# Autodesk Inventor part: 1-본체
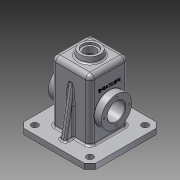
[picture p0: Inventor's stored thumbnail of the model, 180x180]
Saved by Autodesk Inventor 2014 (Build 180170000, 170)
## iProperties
Created: 2016-02
Part Number: 1-본체
Material: 알루미늄 6061
Document SubType Name: Modeling
Designer: HGY
Density: 2.71 g/cm^3
Appearance: 알루미늄 - 평지
Mass: 932.812 g
Surface Area: 1043.48 cm^2
Volume: 344.211 cm^3
Author: HGY
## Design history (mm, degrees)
sketch "스케치1"
  geometry: L1 (-35, 35)-(35, 35); L2 (35, 35)-(35, -35); L3 (35, -35)-(-35, -35); L4 (-35, -35)-(-35, 35); L5 (-35, 35)-(35, -35); L6 (35, 35)-(-35, -35); 1 further point
  constraints: 12 end point, 2 midpoint, 2 parallel, 2 perpendicular, 1 horizontal
  dimensions: "d0" = 70 distance of L1.end L2.end
extrude "돌출1" new body sketch "스케치1" distance "d1" = 120; taper "d2" = 0 deg
sketch "스케치2"
  geometry: L1 (-65, 65)-(65, 65); L2 (65, 65)-(65, -65); L3 (65, -65)-(-65, -65); L4 (-65, -65)-(-65, 65); L5 (-65, 65)-(65, -65); L6 (65, 65)-(-65, -65); 1 further point
  constraints: 12 end point, 2 midpoint, 2 parallel, 2 perpendicular, 1 horizontal
  dimensions: "d3" = 130 distance of L1.end L2.end
extrude "돌출2" join sketch "스케치2" distance "d4" = 10; taper "d5" = 0 deg
fillet "모깎기1" dims "d6" = 8
fillet "모깎기2" dims "d7" = 8
feature "쉘1" dims "d8" = 10, "d9" = 5
sketch "스케치3"
  geometry: L1 (-27, 120)-(27, 120) reference; L2 (35, 112)-(35, 10) reference; L3 (35, 10)-(65, 10) reference; L4 (65, 10)-(65, 0) reference; L5 (65, 0)-(30, 0) reference; L6 (30, 0)-(30, 112) reference; L7 (27, 115)-(-27, 115) reference; L8 (-30, 112)-(-30, 0) reference; L9 (-30, 0)-(-65, 0) reference; L10 (-65, 0)-(-65, 10) reference; L11 (-65, 10)-(-35, 10) reference; L12 (-35, 10)-(-35, 112) reference; L13 (0, 120)-(0, 130); L14 (0, 130)-(-18.237, 130); L15 (-18.237, 130)-(-20, 120); A1 r 8 centre (-27, 112) between (-27, 120) and (-35, 112) reference; A2 r 8 centre (27, 112) between (35, 112) and (27, 120) reference; A3 r 3 centre (27, 112) between (30, 112) and (27, 115) reference; A4 r 3 centre (-27, 112) between (-27, 115) and (-30, 112) reference; 1 further point
  constraints: 6 end point, 1 midpoint, 1 parallel, 1 perpendicular, 1 point on line
  dimensions: "d11" = 10 deg angle of L8 L15; "d13" = 40 diameter of L15.end L13; "d14" = 10 distance between parallel lines of L1 L14
revolve "회전1" sketch "스케치3" stored, may be unused: angle "d15" = 90 deg
sketch "스케치6"
  geometry: C1 r 27.5 at (-45, 27); 1 further point
  constraints: 1 centre point, 1 horizontal alignment
  dimensions: "d26" = 55 diameter of C1; "d27" = 55 distance of C1.centre point (10, 27)
extrude "돌출5" join sketch "스케치6" distance "d28" = 13; taper "d29" = 0 deg
fillet "모깎기5" dims "d30" = 0.5
sketch "스케치8"
  geometry: L1 (35, 112)-(35, 10) reference; L2 (35, 10)-(65, 10) reference; L3 (65, 10)-(65, 0) reference; L4 (65, 0)-(30, 0) reference; L5 (30, 0)-(30, 112) reference; L6 (27, 115)-(-27, 115) reference; L7 (-30, 112)-(-30, 0) reference; L8 (-30, 0)-(-65, 0) reference; L9 (-65, 0)-(-65, 10) reference; L10 (-65, 10)-(-35, 10) reference; L11 (-35, 10)-(-35, 27) reference; L12 (-35.5, 27.5)-(-48, 27.5) reference; L13 (-48, 27.5)-(-48, 82.5) reference; L14 (-48, 82.5)-(-35.5, 82.5) reference; L15 (-35, 83)-(-35, 112) reference; L16 (-27, 120)-(-20, 120) reference; L17 (-20, 120)-(-18.237, 130) reference; L18 (-18.237, 130)-(18.237, 130) reference; L19 (18.237, 130)-(20, 120) reference; L20 (20, 120)-(27, 120) reference; L21 (-30, 55)-(-23, 55); L22 (-23, 55)-(-23, 75.5); L23 (-23, 75.5)-(-30, 82.5); A1 r 8 centre (27, 112) between (35, 112) and (27, 120) reference; A2 r 3 centre (27, 112) between (30, 112) and (27, 115) reference; A3 r 3 centre (-27, 112) between (-27, 115) and (-30, 112) reference; A4 r 0.5 centre (-35.5, 27) between (-35, 27) and (-35.5, 27.5) reference; A5 r 0.5 centre (-35.5, 83) between (-35.5, 82.5) and (-35, 83) reference; A6 r 8 centre (-27, 112) between (-27, 120) and (-35, 112) reference; 3 further points
  constraints: 6 end point, 2 midpoint, 2 point on line, 1 horizontal alignment, 1 parallel, 1 perpendicular
  dimensions: "d31" = 135 deg angle of L7 L23; "d32" = 55 diameter of L23.end L21; "d33" = 7 distance between parallel lines of L7 L22
revolve "회전2" sketch "스케치8" stored, may be unused: angle "d34" = 90 deg
hole "구멍1" diameter "d37" = 32; stored, may be unused: countersink angle "d41" = 90 deg, drill point angle "d43" = 118 deg; dims "d35" = 10, "d36" = 10, "d38" = 6, "d39" = 4, "d40" = 2, "d42" = 8
sketch "스케치9"
  geometry: L1 (0, 0)-(-22.5, 0); C1 r 27.5 at (0, 0) reference; 1 further point
  constraints: 2 end point, 1 horizontal
  dimensions: "d44" = 22.5 distance of L1.start L1.end
hole "구멍2" sketch "스케치9" at (-22.5, 0) diameter "d45" = 3.242; stored, may be unused: countersink angle "d49" = 90 deg, drill point angle "d51" = 118 deg; dims "d46" = 8, "d47" = 4, "d48" = 2, "d50" = 10
fillet "모깎기6" dims "d55" = 0.5
sketch "스케치10"
  geometry: L1 (-18.237, 130)-(18.237, 130) reference; L2 (18.237, 130)-(20, 120) reference; L3 (20, 120)-(27, 120) reference; L4 (35, 112)-(35, 10) reference; L5 (35, 10)-(65, 10) reference; L6 (65, 10)-(65, 0) reference; L7 (65, 0)-(30, 0) reference; L8 (30, 0)-(30, 112) reference; L9 (27, 115)-(-27, 115) reference; L10 (-30, 112)-(-30, 0) reference; L11 (-30, 0)-(-65, 0) reference; L12 (-65, 0)-(-65, 10) reference; L13 (-65, 10)-(-35, 10) reference; L14 (-35, 10)-(-35, 112) reference; L15 (-27, 120)-(-20, 120) reference; L16 (-20, 120)-(-18.237, 130) reference; L17 (-50, 10)-(-35, 95.069); A1 r 8 centre (27, 112) between (35, 112) and (27, 120) reference; A2 r 3 centre (27, 112) between (30, 112) and (27, 115) reference; A3 r 3 centre (-27, 112) between (-27, 115) and (-30, 112) reference; A4 r 8 centre (-27, 112) between (-27, 120) and (-35, 112) reference; 1 further point
  constraints: 2 end point, 1 midpoint, 1 point on line
  dimensions: "d56" = 15 distance of L17.start L12.end; "d57" = 10 deg angle of L12 L17
feature "리브1" sketch "스케치10" dims "d58" = 1, "d59" = 10, "d60" = 0, "d61" = 0, "d62" = 1, "d63" = 1
fillet "모깎기7" dims "d64" = 3
fillet "모깎기8" dims "d65" = 3
chamfer "모따기1" distance "d66" = 1; stored, may be unused: second distance "d67" = 2, angle "d68" = 45 deg
hole "구멍3" diameter "d71" = 21; stored, may be unused: countersink angle "d75" = 90 deg, drill point angle "d77" = 118 deg; dims "d69" = 10, "d70" = 10, "d72" = 8, "d73" = 28, "d74" = 4, "d76" = 10
sketch "스케치11"
  geometry: L1 (-50, -50)-(50, -50); L2 (50, -50)-(50, 50); L3 (50, 50)-(-50, 50); L4 (-50, 50)-(-50, -50); L5 (-50, -50)-(50, 50); L6 (50, -50)-(-50, 50); 1 further point
  constraints: 12 end point, 2 midpoint, 2 parallel, 2 perpendicular, 1 horizontal
  dimensions: "d78" = 100 distance of L2.end L3.end
hole "구멍4" sketch "스케치11" at (-50, -50), (50, 50), (50, -50), (-50, 50) diameter "d79" = 12; stored, may be unused: countersink angle "d83" = 90 deg, drill point angle "d85" = 118 deg; dims "d80" = 8, "d81" = 28, "d82" = 4, "d84" = 10
chamfer "모따기2" distance "d86" = 10; stored, may be unused: second distance "d87" = 2, angle "d88" = 45 deg
fillet "모깎기9" dims "d89" = 3
sketch "스케치12"
  geometry: L1 (-8, 54)-(-8, 0) reference; L2 (99, 62)-(0, 62) reference; 2 further points
  constraints: 1 other
  dimensions: "d90" = 30 distance from line of L1 point (22, 27); "d91" = 35 distance from line of L2 point (22, 27)
feature "엠보싱1" sketch "스케치12" dims "d0" = 70, "d7" = 8, "d92" = 0.5, "d93" = 0
fillet "모깎기10" dims "d94" = 3
fillet "모깎기11" dims "d95" = 0.5
node "솔리드1"
pattern_circular "원형 패턴1" dims angle "d53" = 360 deg
mirror "대칭1"
mirror "대칭2"
node "절단 모서리 투영1"
node "절단 모서리 투영2"
node "절단 모서리 투영3"
